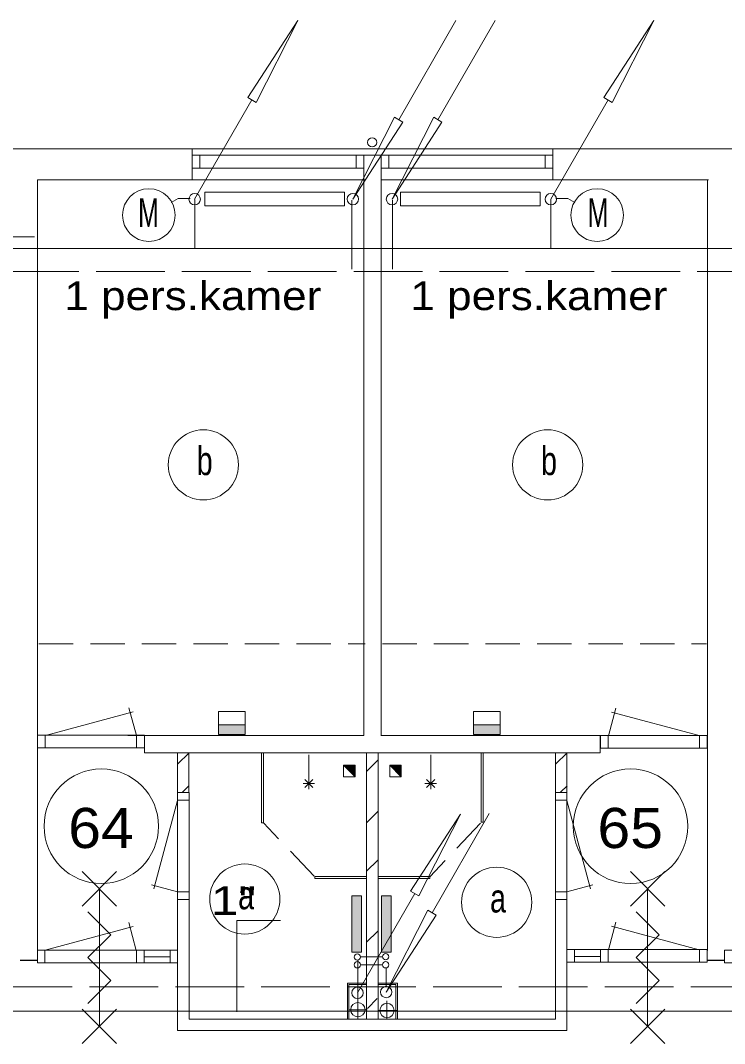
# Model space of a CAD drawing. Extents: x 295824 to 414724, y 24924 to 109024.
# Drawn here: x 313941 to 320090, y 39720 to 48648 of the extents above; entities that cross this region are included whole.
import ezdxf
from ezdxf.enums import TextEntityAlignment as Align

# ---------------------------------------------------------------- set-up
doc = ezdxf.new("R2010")
doc.units = 0
doc.header["$LTSCALE"] = 100
for name, pattern in [('DOT_DASHED', [7.7, 5, -1.2, 0.3, -1.2]), ('LONG_DASHED', [7.5, 6, -1.5]), ('MEDIUM_DASHED', [4.5, 3, -1.5])]:
    doc.linetypes.add(name, pattern=pattern)
doc.layers.add('16', color=7, linetype='Continuous', lineweight=13)
doc.layers.add('61', color=7, linetype='Continuous', lineweight=13)

msp = doc.modelspace()

# ---------------------------------------------------------------- hatches: boundary and pattern name
at = {"layer": '16'}
for points in [[(315902.2, 42415.9), (315670.7, 42415.9), (315670.7, 42502.4), (315902.2, 42502.4)], [(318129.9, 42415.9), (317898.4, 42415.9), (317898.4, 42502.4), (318129.9, 42502.4)], [(316835.4, 41008.8), (316920.8, 41008.8), (316920.8, 40516.6), (316835.4, 40516.6)], [(317094.6, 41008.8), (317180, 41008.8), (317180, 40516.6), (317094.6, 40516.6)]]:
    msp.add_hatch(color=256, dxfattribs=at).paths.add_polyline_path(points)
at = {"layer": '61'}
for points in [[(316862.8, 42048.6), (316762.8, 42148.6), (316862.8, 42148.6)], [(317265.8, 42048.6), (317165.8, 42148.6), (317265.8, 42148.6)]]:
    msp.add_hatch(color=256, dxfattribs=at).paths.add_polyline_path(points)

# ---------------------------------------------------------------- linework, layer by layer
at = {"layer": '16'}
for p, q in [((317744.5, 48648), (317244.5, 47782)), ((318086.1, 48648), (317586.1, 47782)), ((315462.6, 47087.9), (315962.6, 47953.9)), ((318572.9, 47087.9), (319072.9, 47953.9)), ((315462.9, 47084.6), (315462.9, 46658)), ((318573.2, 47084.6), (318573.2, 46658)), ((313558.7, 46759.1), (314063.8, 46759.1)), ((303410.7, 46658), (326194, 46658)), ((309466.3, 46658), (325376.7, 46658)), ((315670.7, 42502.4), (315670.7, 42616.3)), ((317898.4, 42502.4), (317898.4, 42616.3)), ((318035.8, 41727.8), (317535.8, 40861.8)), ((316884.2, 40162.9), (317384.2, 41028.9)), ((316887.6, 40005.9), (316887.6, 40446)), ((317103, 40477.8), (316911.2, 40477.8)), ((326194, 40002.8), (302570.9, 40002.8))]:
    msp.add_line(p, q, dxfattribs=at)
at = {"layer": '16', "linetype": 'LONG_DASHED'}
for p, q in [((316835.5, 47078.4), (316835.5, 46458)), ((317188.9, 47078.4), (317188.9, 46458)), ((304851.7, 46458), (326394, 46458)), ((316911.4, 40407.1), (317102.9, 40407.1)), ((317133.8, 40217.7), (317133.8, 40381.3)), ((326394, 40214.6), (302769.9, 40214.6))]:
    msp.add_line(p, q, dxfattribs=at)
at = {"layer": '16'}
for points in [[(316362.6, 48646.9), (315998.6, 47932.9), (315926.6, 47974.9)], [(319472.9, 48646.9), (319108.9, 47932.9), (319036.9, 47974.9)], [(316844.5, 47089), (317208.5, 47803), (317280.5, 47761)], [(317186.1, 47089), (317550.1, 47803), (317622.1, 47761)], [(315551.3, 47031.2), (316770.7, 47031.2), (316770.7, 47149.1), (315551.3, 47149.1)], [(317259.6, 47031.2), (318478.9, 47031.2), (318478.9, 47149.1), (317259.6, 47149.1)], [(315902.2, 42415.9), (315670.7, 42415.9), (315670.7, 42502.4), (315902.2, 42502.4)], [(318129.9, 42415.9), (317898.4, 42415.9), (317898.4, 42502.4), (318129.9, 42502.4)], [(317784.2, 41721.9), (317420.2, 41007.9), (317348.2, 41049.9)], [(316835.4, 41008.8), (316920.8, 41008.8), (316920.8, 40516.6), (316835.4, 40516.6)], [(317094.6, 41008.8), (317180, 41008.8), (317180, 40516.6), (317094.6, 40516.6)], [(317135.8, 40168.8), (317499.8, 40882.8), (317571.8, 40840.8)]]:
    msp.add_lwpolyline(points, close=True, dxfattribs=at)
for points in [[(315423.8, 47094.6), (315317.8, 47094.6), (315258.3, 47060.2)], [(318616.5, 47094.6), (318722.6, 47094.6), (318782.1, 47060.2)], [(315902.2, 42502.4), (315902.2, 42616.3), (315670.7, 42616.3)], [(318129.9, 42502.4), (318129.9, 42616.3), (317898.4, 42616.3)], [(315829.7, 39996.4), (315829.7, 40792.7), (316212.4, 40792.7)]]:
    msp.add_lwpolyline(points, dxfattribs=at)
for centre, radius in [((315062.7, 46949.2), 229.9), ((318977.7, 46949.2), 229.9), ((315462.6, 47087.6), 50), ((316844.5, 47089.3), 50), ((317186.1, 47089.3), 50), ((318572.9, 47087.6), 50), ((316883.5, 40474.8), 27.9), ((317130.9, 40477.8), 27.9), ((316883.5, 40407), 27.9), ((317130.9, 40407), 27.9), ((316884.2, 40162.6), 50), ((317135.8, 40169.1), 50)]:
    msp.add_circle(centre, radius, dxfattribs=at)
at = {"layer": '61'}
for p, q in [((301828.9, 47527.9), (333452, 47527.9)), ((313820.3, 47527.9), (333174.1, 47527.9)), ((315441, 47257.3), (315441, 47527.3)), ((318589.9, 47257.3), (318589.9, 47527.3)), ((315441.8, 47472.1), (316940.8, 47472.1)), ((315441.8, 47358.1), (315441.8, 47472.1)), ((315508.8, 47358.1), (315508.8, 47471.5)), ((316873.8, 47472.1), (318589.8, 47472.1)), ((316873.8, 47358.5), (316873.8, 47472.1)), ((316940.8, 47359.1), (316940.8, 47472.1)), ((316941, 47257.3), (316941, 47472.1)), ((317089.9, 47257.3), (317089.9, 47472.1)), ((317090.8, 47358.1), (317090.8, 47472.1)), ((317157.8, 47358.1), (317157.8, 47471.5)), ((318522.8, 47358.5), (318522.8, 47471.5)), ((318589.8, 47359.1), (318589.8, 47472.1)), ((315441.8, 47358.1), (316939.9, 47358.1)), ((317090.8, 47358.1), (318588.8, 47358.1)), ((314090.1, 40532.9), (314090.1, 47257.9)), ((314098.9, 47257.9), (316948.9, 47257.9)), ((319948.9, 47257.9), (317098.9, 47257.9)), ((319940.1, 40532.9), (319940.1, 47257.9)), ((314158.7, 42409.2), (314926, 42614.8)), ((314953.3, 42407.1), (314888.2, 42649.8)), ((319075.1, 42405.1), (319140.1, 42647.8)), ((319869.6, 42407.2), (319102.3, 42612.8)), ((314156.1, 42299.1), (314156.1, 42409.1)), ((314956.1, 42299.1), (314956.1, 42409.1)), ((315023.1, 42299.1), (315023.1, 42409.1)), ((316938.8, 42407.9), (314878.8, 42407.9)), ((317088.7, 42407.9), (319031.2, 42407.9)), ((317088.8, 42407.9), (319938, 42407.9)), ((319005.2, 42297.1), (319005.2, 42407.1)), ((319072.2, 42297.1), (319072.2, 42407.1)), ((319872.2, 42297.1), (319872.2, 42407.1)), ((319938.1, 42297.4), (319938.1, 42407.8)), ((315021, 42299.4), (314090.2, 42299.4)), ((315024, 42257.9), (318614.2, 42257.9)), ((315313.8, 41911.5), (315313.8, 42257.9)), ((315313.8, 42157.2), (315414.2, 42257.6)), ((315412.5, 41911.5), (315412.5, 42257.9)), ((316046.5, 41644.6), (316046.5, 42253)), ((316064.5, 41644.6), (316064.5, 42253)), ((316459.4, 42039.2), (316459.4, 42239.2)), ((316963.7, 42257.9), (316963.7, 39932.9)), ((317063.7, 42257.9), (317063.7, 39932.9)), ((317523.8, 42039.2), (317523.8, 42239.2)), ((317964.3, 41650.7), (317964.3, 42255.5)), ((317982.3, 41650.7), (317982.3, 42255.5)), ((318614.2, 41911.9), (318614.2, 42258.3)), ((318614.3, 42157.2), (318714.7, 42257.6)), ((318713.9, 41911.5), (318713.9, 42257.9)), ((319007.3, 42297.4), (319938.1, 42297.4)), ((316964.2, 42093), (317062.7, 42191.5)), ((315356.2, 41913.2), (315412.8, 41969.9)), ((316509.4, 41989.2), (316409.4, 41989.2)), ((316494.7, 42024.5), (316424, 41953.8)), ((316494.7, 41953.8), (316424, 42024.5)), ((316459.4, 42039.2), (316459.4, 41939.2)), ((317573.8, 41989.2), (317473.8, 41989.2)), ((317559.2, 42024.5), (317488.5, 41953.8)), ((317559.2, 41953.8), (317488.5, 42024.5)), ((317523.8, 42039.2), (317523.8, 41939.2)), ((318658.1, 41913.2), (318714.7, 41969.9)), ((315313.6, 40977.9), (315313.6, 41911.9)), ((315413.6, 41911.9), (315313.6, 41911.9)), ((315413.6, 41911.9), (315413.6, 40977.9)), ((318613.7, 41911.5), (318613.7, 40977.5)), ((318614.2, 41911.5), (318714.3, 41911.5)), ((318713.7, 40976.7), (318713.7, 41911.5)), ((315313.8, 41841.3), (315106.9, 41069.1)), ((315413.7, 41844.9), (315313.6, 41844.9)), ((318613.6, 41844.5), (318713.7, 41844.5)), ((318713.4, 41841), (318920.4, 41068.7)), ((316964.2, 41645.4), (317062.7, 41743.9)), ((316046.5, 41644.6), (316064.5, 41644.6)), ((317964.3, 41650.7), (317982.3, 41650.7)), ((318713.8, 41578.4), (318713.8, 41468)), ((316964.2, 41222.9), (317062.7, 41321.4)), ((314480.6, 40919.8), (314780.6, 41219.8)), ((314780.6, 40919.8), (314480.6, 41219.8)), ((317514.8, 41176.7), (317064.7, 41176.7)), ((317514.8, 41176.7), (317514.8, 41158.7)), ((319268.3, 40919.8), (319568.3, 41219.8)), ((319568.3, 40919.8), (319268.3, 41219.8)), ((314630.6, 41069.8), (314630.6, 39869.8)), ((315313.8, 41043.9), (315086.5, 41104.8)), ((316963.4, 41158.7), (316513, 41158.7)), ((317514.8, 41158.7), (317064.7, 41158.7)), ((318713.4, 41043.5), (318940.8, 41104.4)), ((319418.3, 41069.8), (319418.3, 39869.8)), ((315413.5, 41044.9), (315314.1, 41044.9)), ((318613.8, 41044.5), (318713.2, 41044.5)), ((315413.6, 40977.9), (315313.6, 40977.9)), ((315313.7, 40975.3), (315313.7, 40188.2)), ((315413.7, 40638.2), (315413.7, 40975.3)), ((318613.7, 40977.5), (318613.7, 39932.9)), ((318613.7, 40977.5), (318713.7, 40977.5)), ((318713.7, 40977.5), (318713.7, 40532.9)), ((314157.5, 40535.1), (314924.8, 40740.7)), ((314952, 40532.9), (314887, 40775.7)), ((319075.1, 40536.8), (319140.1, 40779.5)), ((319869.6, 40539), (319102.3, 40744.6)), ((316964.2, 40603), (317062.7, 40701.4)), ((314154.9, 40424.9), (314154.9, 40534.9)), ((314954.9, 40424.9), (314954.9, 40534.9)), ((315021.9, 40424.9), (315021.9, 40534.9)), ((315247.4, 40424.9), (315247.4, 40534.9)), ((318779.7, 40428.8), (318779.7, 40538.8)), ((319005.2, 40428.8), (319005.2, 40538.8)), ((319072.2, 40428.8), (319072.2, 40538.8)), ((319872.2, 40428.8), (319872.2, 40538.8)), ((313940.2, 40447.3), (314090.2, 40447.3)), ((313942.3, 40447.3), (314092.3, 40447.3)), ((315022.7, 40475.7), (315247.4, 40475.7)), ((319004.4, 40479.6), (318779.7, 40479.6)), ((319939.7, 40447.3), (320089.7, 40447.3)), ((313940.2, 40443.5), (314090.2, 40443.5)), ((313942.3, 40443.5), (314092.3, 40443.5)), ((319939.7, 40443.5), (320089.7, 40443.5)), ((316795.9, 40248), (316963.6, 40248)), ((316795.9, 40248), (316795.9, 39932.9)), ((316810.2, 40234.4), (316963.6, 40234.4)), ((316810.2, 40234.4), (316810.2, 39934)), ((317063.7, 40234.4), (317218.4, 40234.4)), ((317064.7, 40248), (317233.4, 40248)), ((317218.4, 39932.9), (317218.4, 40234.4)), ((317233.4, 39932.9), (317233.4, 40248)), ((316971.7, 40026.8), (317057, 40112.1)), ((314480.6, 39719.8), (314780.6, 40019.8)), ((314780.6, 39719.8), (314480.6, 40019.8)), ((319268.3, 39719.8), (319568.3, 40019.8)), ((319568.3, 39719.8), (319268.3, 40019.8))]:
    msp.add_line(p, q, dxfattribs=at)
at = {"layer": '61', "linetype": 'MEDIUM_DASHED'}
for p, q in [((314101.9, 43208.1), (316951.9, 43208.1)), ((317102.6, 43208.1), (319932.3, 43208.1)), ((316505.7, 41179.8), (316063.8, 41644.8)), ((317959.9, 41643.1), (317515.9, 41175.8))]:
    msp.add_line(p, q, dxfattribs=at)
at = {"layer": '61', "linetype": 'DOT_DASHED'}
for p, q in [((316888.9, 39934.8), (316888.9, 40098.9)), ((317141.8, 39933.5), (317141.8, 40092.8)), ((316967.7, 40015.2), (316815.1, 40015.2)), ((316963, 40015.2), (316826, 40015.2)), ((317227.5, 40007.7), (317063.4, 40007.7)), ((317213.7, 40007.7), (317085.8, 40007.7))]:
    msp.add_line(p, q, dxfattribs=at)
at = {"layer": '61'}
for points in [[(314090.2, 47257.9), (316940.2, 47257.9), (316940.2, 42407.9)], [(314090.3, 47257.9), (316940.3, 47257.9), (316940.3, 42407.9)], [(319940.2, 47257.9), (317090.2, 47257.9), (317090.2, 42407.9)], [(319940.3, 47257.9), (317090.3, 47257.9), (317090.3, 42407.9)], [(314090.2, 42299.4), (314090.2, 42409.8), (315023.5, 42409.8)], [(316938.7, 42407.9), (315024, 42407.9), (315024, 42257.9)], [(319004.8, 42407.8), (319004.8, 42257.9), (318599.4, 42257.9)], [(316762.8, 42148.6), (316862.8, 42148.6), (316862.8, 42048.6)], [(317165.8, 42148.6), (317265.8, 42148.6), (317265.8, 42048.6)], [(316963.4, 41176.7), (316513, 41176.7), (316513, 41158.7)], [(315413.7, 41158.7), (315413.7, 39932.9), (317293.7, 39932.9)], [(314530.6, 40869.8), (314730.6, 40669.8), (314530.6, 40469.8), (314730.6, 40269.8), (314530.6, 40069.8)], [(317088.5, 39932.9), (318613.7, 39932.9), (318613.7, 40882.9)], [(319318.3, 40869.8), (319518.3, 40669.8), (319318.3, 40469.8), (319518.3, 40269.8), (319318.3, 40069.8)], [(315313.7, 40432.9), (315313.7, 39832.9), (318713.7, 39832.9), (318713.7, 40432.9)]]:
    msp.add_lwpolyline(points, dxfattribs=at)
for points in [[(316762.8, 42148.6), (316762.8, 42048.6), (316862.8, 42048.6)], [(316862.8, 42048.6), (316762.8, 42148.6), (316862.8, 42148.6)], [(317165.8, 42148.6), (317165.8, 42048.6), (317265.8, 42048.6)], [(317265.8, 42048.6), (317165.8, 42148.6), (317265.8, 42148.6)], [(314089, 40425.3), (314089, 40535.6), (315313.3, 40535.6), (315313.3, 40425.3)], [(319938.1, 40429.1), (319938.1, 40539.5), (318713.8, 40539.5), (318713.8, 40429.1)], [(320089.2, 40425.3), (320089.2, 40535.6), (321313.5, 40535.6), (321313.5, 40425.3)]]:
    msp.add_lwpolyline(points, close=True, dxfattribs=at)
for centre, radius in [((317012.8, 47584.2), 40), ((315538.5, 44769.7), 306.3), ((318545.3, 44769.7), 306.3), ((314647.4, 41615.9), 500), ((319269, 41615.9), 500), ((315900.4, 40980.6), 306.3), ((318099.9, 40952.7), 306.3), ((316887.7, 40015.2), 62.5), ((317141.8, 40008.4), 62.5)]:
    msp.add_circle(centre, radius, dxfattribs=at)

# ---------------------------------------------------------------- texts
at = {"layer": '16'}
for s, width, p in [('M', 0.65, (314968.7, 46846.2)), ('M', 0.65, (318894.5, 46846.2)), (' 1"', 1.3, (315483, 40842.9))]:
    msp.add_text(s, height=250, dxfattribs=dict(at, width=width)).set_placement(p)
at = {"layer": '61'}
for s, width, p in [('1 pers.kamer', 1.15, (314324.7, 46120.2)), ('1 pers.kamer', 1.15, (317346.9, 46120.2)), ('b', 0.75, (315480.5, 44680.6)), ('b', 0.75, (318487.3, 44680.6)), ('a', 0.75, (315842.4, 40891.4)), ('a', 0.75, (318041.9, 40863.5))]:
    msp.add_text(s, height=250, dxfattribs=dict(at, width=width)).set_placement(p)
at = {"layer": '61', "width": 1.1}
for s, p in [('64', (314644.4, 41426)), ('65', (319266.1, 41426))]:
    msp.add_text(s, height=350, dxfattribs=at).set_placement(p, align=Align.CENTER)

doc.saveas('drawing.dxf')
